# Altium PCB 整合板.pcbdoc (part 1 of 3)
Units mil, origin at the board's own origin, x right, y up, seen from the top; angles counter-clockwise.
Board outline 5095 x 5568.76 mil, 2 copper layers (Top Layer, Bottom Layer); 124 components, 78 nets, 425 pads, 497 vias.
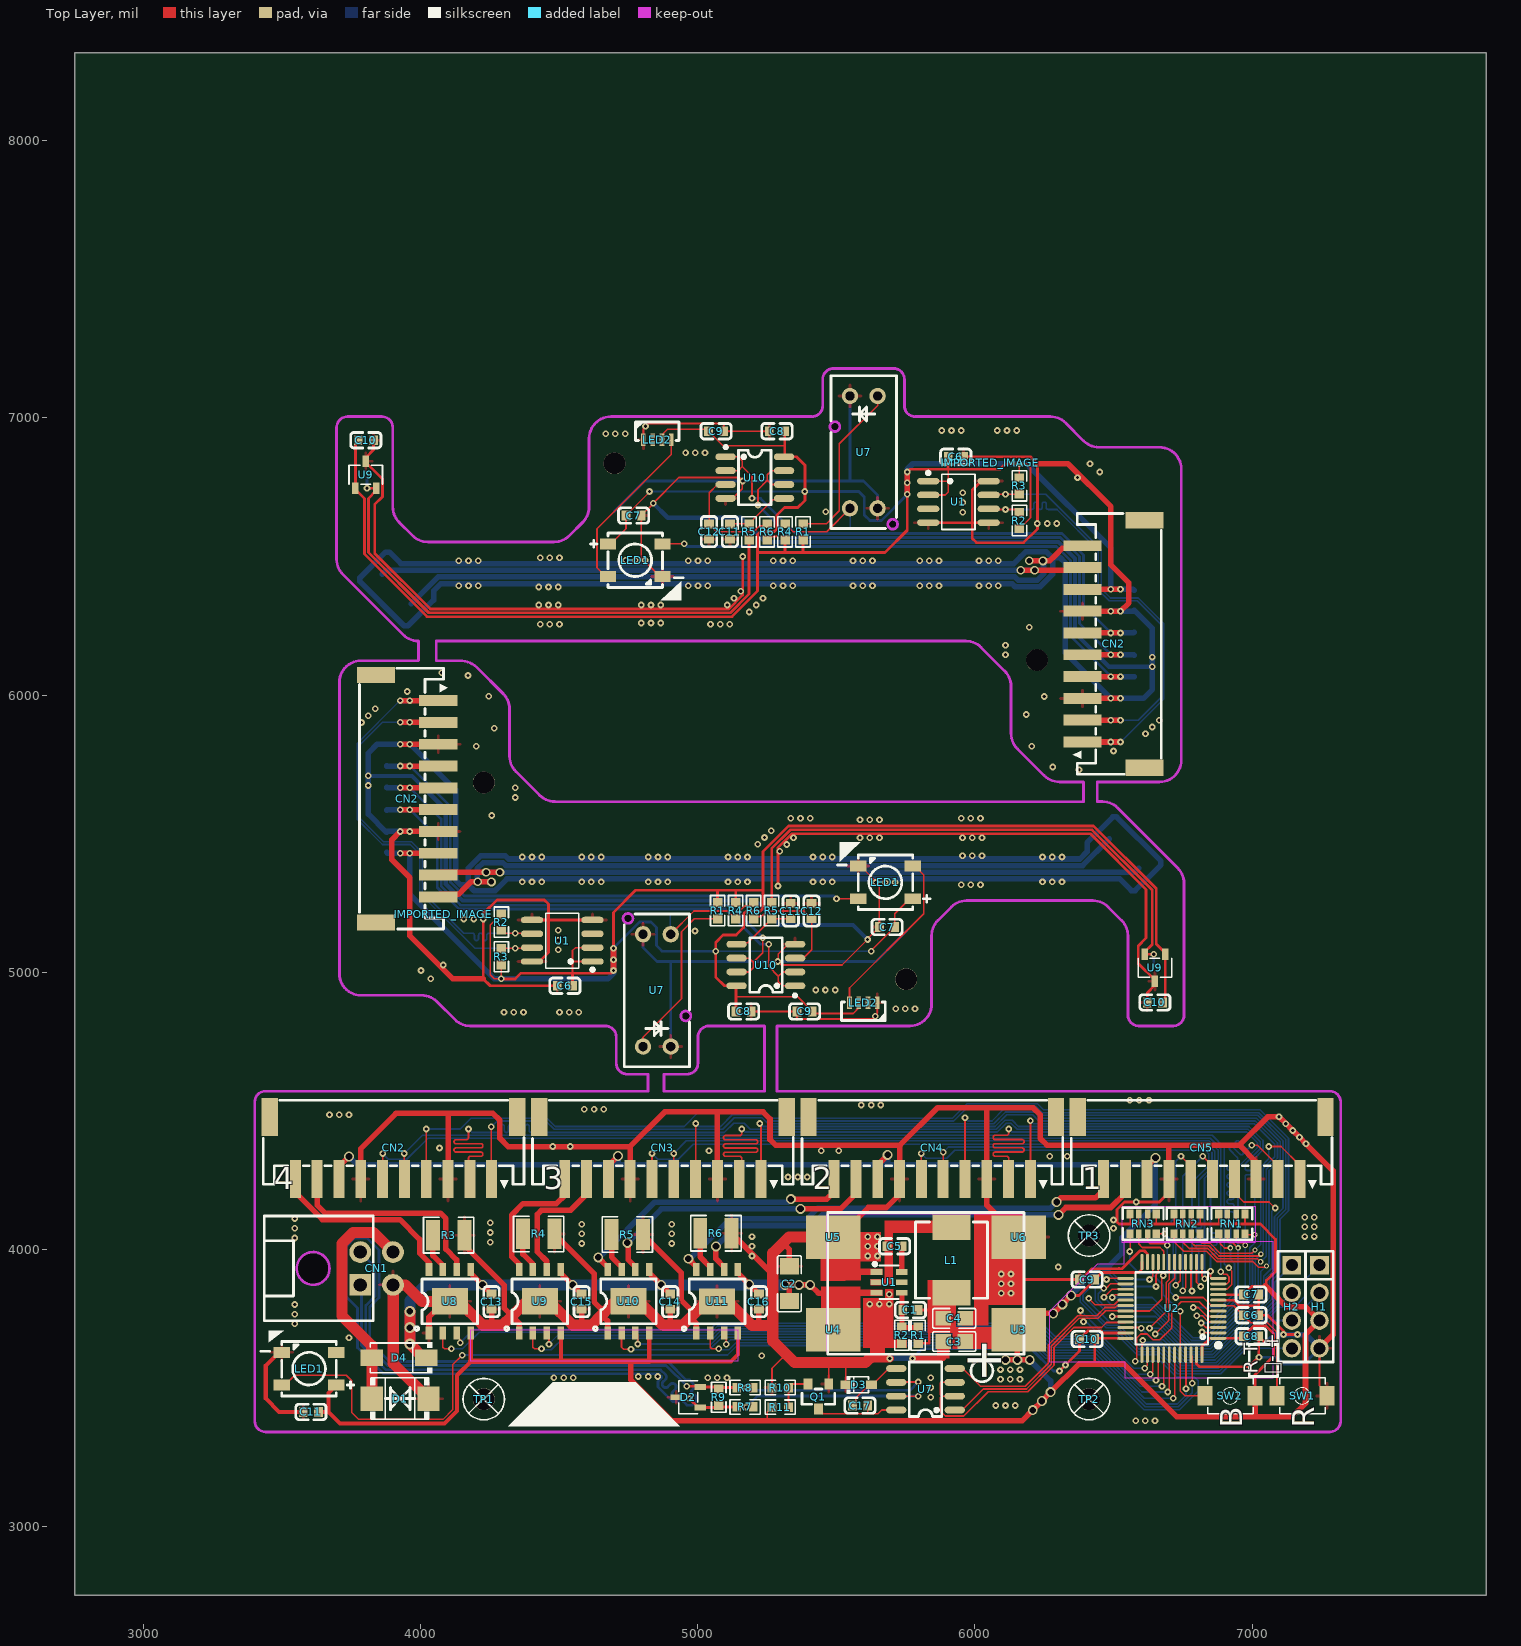
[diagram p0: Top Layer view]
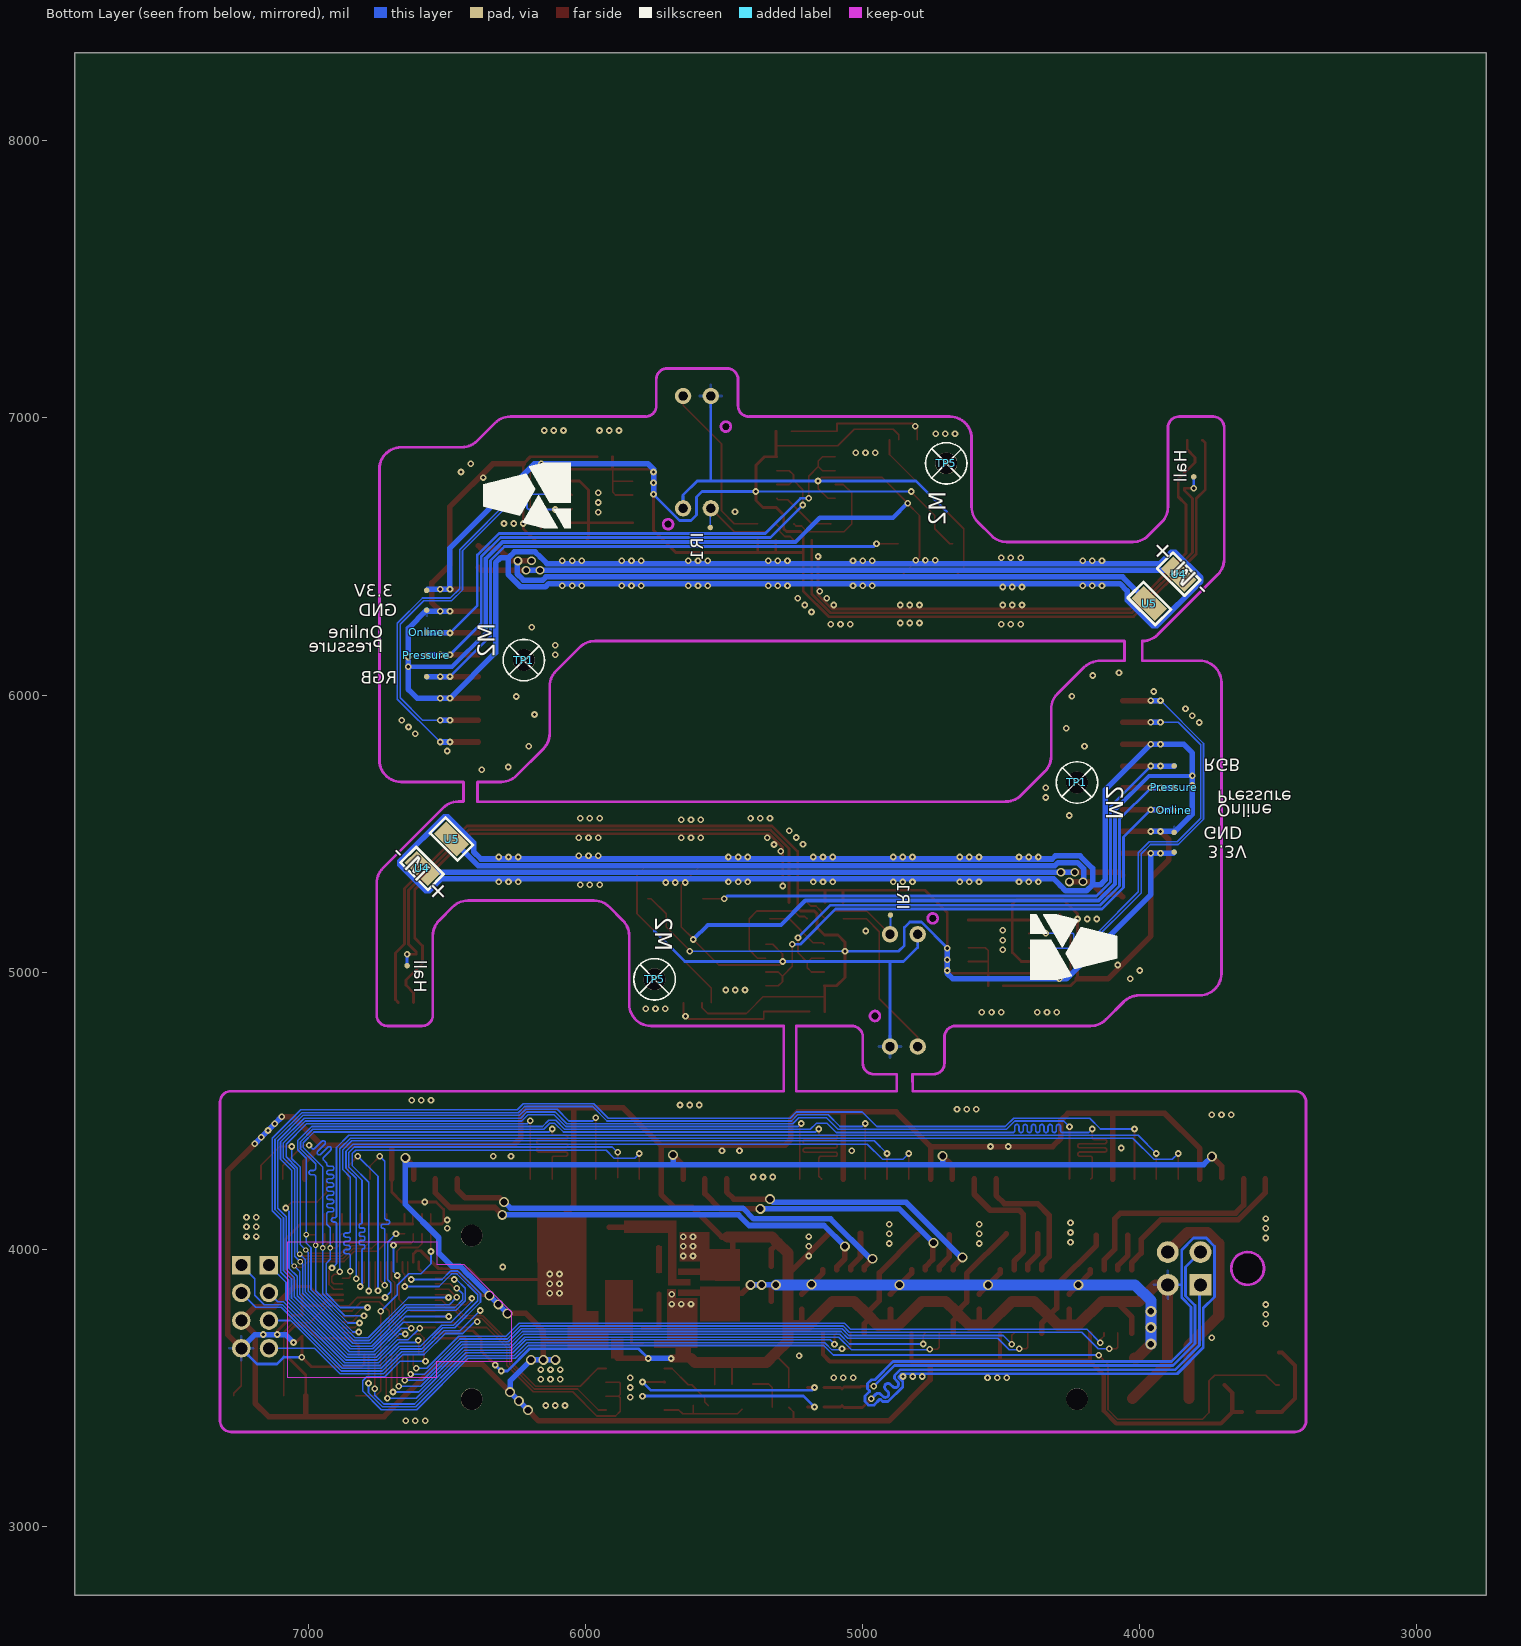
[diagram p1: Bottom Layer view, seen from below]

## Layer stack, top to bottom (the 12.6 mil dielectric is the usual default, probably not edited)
Top Layer: signal copper (thickness not stored)
Dielectric: dielectric 12.6, FR-4, Dk 4.8
Bottom Layer: signal copper (thickness not stored)

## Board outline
7845,2750 2750,2750 2750,8318.76 7845,8318.76

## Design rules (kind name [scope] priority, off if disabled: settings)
BoardOutlineClearance copperThickness1oz [All] p0: genericclearance=10 ignorepadtopadclearanceinfootprint=FALSE except(0: Arc-SplitContinuation Track-SplitContinuation SMDPad-SplitContinuation THPad-SplitContinuation Via-SplitContinuation Fill-SplitContinuation Poly-SplitContinuation Region-SplitContinuation Text-SplitContinuation; 6: Track-CutoutEdge SMDPad-CutoutEdge THPad-CutoutEdge Via-CutoutEdge Region-CutoutEdge; 11.8: Track-OutlineEdge SMDPad-OutlineEdge THPad-OutlineEdge Via-OutlineEdge Fill-OutlineEdge Region-OutlineEdge Poly-OutlineEdge Text-OutlineEdge Fill-CutoutEdge)
BoardOutlineClearance copperThickness2oz [All] p0: genericclearance=10 ignorepadtopadclearanceinfootprint=FALSE except(0: Arc-SplitContinuation Track-SplitContinuation SMDPad-SplitContinuation THPad-SplitContinuation Via-SplitContinuation Fill-SplitContinuation Poly-SplitContinuation Region-SplitContinuation Text-SplitContinuation; 6: Track-CutoutEdge SMDPad-CutoutEdge THPad-CutoutEdge Via-CutoutEdge Region-CutoutEdge; 11.8: Track-OutlineEdge SMDPad-OutlineEdge THPad-OutlineEdge Via-OutlineEdge Fill-OutlineEdge Region-OutlineEdge Poly-OutlineEdge Text-OutlineEdge Fill-CutoutEdge)
Clearance copperThickness1oz [(InNet('MCU_SCL') OR InNet('MCU_SDA') OR InNet('GND') OR InNet('RGB_OUT') OR InNet('K_PULL') OR InNet('K_ONLINE') OR InNet('3.3V') OR InNet('HALL_OUT') OR InNet('$1N10852') OR InNet('MOTOR_HOUT') OR InNet('MOTOR_LOUT') OR InNet('IR1_RECV') OR InNet('IR1_RC') OR InNet('HALL_RC') OR InNet('$1N13047') OR InNet('$1N2756') OR InNet('$1N32182') OR InNet('MCU_RX') OR InNet('$1N22933') OR InNet('RS485_B') OR InNet('$1N32139') OR InNet('$1N1340') OR InNet('MCU_RTS') OR InNet('BOOT0') OR InNet('MOTOR3_L') OR InNet('MOTOR3_H') OR InNet('$1N22936') OR InNet('RS485_A') OR InNet('MOTOR4_H') OR InNet('NRST') OR InNet('MOTOR2_L') OR InNet('SYS_RGB') OR InNet('MOTOR4_L') OR InNet('$1N32717') OR InNet('MOTOR2_H') OR InNet('MOTOR1_L') OR InNet('MCU_TX') OR InNet('MOTOR1_H') OR InNet('24V') OR InNet('SWCLK') OR InNet('MCU_SDA1') OR InNet('RGB_OUT1') OR InNet('SWIO') OR InNet('MCU_SDA2') OR InNet('$1N6554') OR InNet('RGB_OUT2') OR InNet('MCU_SDA3') OR InNet('MCU_SDA4') OR InNet('RGB_OUT4') OR InNet('RGB_OUT3') OR InNet('MCU_SCL4') OR InNet('MCU_SCL3') OR InNet('K_PULL1') OR InNet('K_PULL4') OR InNet('K_ONLINE3') OR InNet('MCU_SCL2') OR InNet('K_PULL3') OR InNet('K_ONLINE1') OR InNet('K_ONLINE4') OR InNet('EXIT_TX') OR InNet('$1N2752') OR InNet('MCU_SCL1') OR InNet('EXIT_RX') OR InNet('K_PULL2') OR InNet('K_ONLINE2') OR InNet('$1N18276') OR InNet('MOTOR4_LOUT') OR InNet('MOTOR4_HOUT') OR InNet('$1N18070') OR InNet('MOTOR3_HOUT') OR InNet('MOTOR3_LOUT') OR InNet('$1N17664') OR InNet('MOTOR2_LOUT') OR InNet('$1N17864') OR InNet('MOTOR1_LOUT') OR InNet('MOTOR2_HOUT') OR InNet('MOTOR1_HOUT') OR InNet('BOOT1'))] p1: gap=7 ignorepadtopadclearanceinfootprint=FALSE except(4: Track-Track; 6: Track-SMDPad SMDPad-SMDPad Track-THPad SMDPad-THPad THPad-THPad Track-Via SMDPad-Via THPad-Via Via-Via SMDPad-Fill THPad-Fill Via-Fill Fill-Fill Track-Region SMDPad-Region THPad-Region Via-Region Region-Region Track-Poly SMDPad-Poly THPad-Poly Via-Poly Fill-Poly Region-Poly Poly-Poly Track-Text SMDPad-Text THPad-Text Via-Text Fill-Text Region-Text Poly-Text Text-Text; 6.9: Track-Hole SMDPad-Hole THPad-Hole Via-Hole Fill-Hole Region-Hole Poly-Hole Text-Hole Sheet-Hole; 11.8: Track-Fill Fill-Region Track-Sheet SMDPad-Sheet THPad-Sheet Via-Sheet Fill-Sheet Region-Sheet Poly-Sheet Text-Sheet)
Clearance copperThickness2oz [All] p1: gap=7 ignorepadtopadclearanceinfootprint=FALSE except(6: Track-SMDPad SMDPad-SMDPad Track-THPad SMDPad-THPad THPad-THPad Track-Via SMDPad-Via THPad-Via Via-Via SMDPad-Fill THPad-Fill Via-Fill Fill-Fill Track-Region SMDPad-Region THPad-Region Via-Region Region-Region Track-Poly SMDPad-Poly THPad-Poly Via-Poly Fill-Poly Region-Poly Poly-Poly Track-Text SMDPad-Text THPad-Text Via-Text Fill-Text Region-Text Poly-Text Text-Text; 6.9: Track-Hole SMDPad-Hole THPad-Hole Via-Hole Fill-Hole Region-Hole Poly-Hole Text-Hole Sheet-Hole; 8: Track-Track; 11.8: Track-Fill Fill-Region Track-Sheet SMDPad-Sheet THPad-Sheet Via-Sheet Fill-Sheet Region-Sheet Poly-Sheet Text-Sheet)
DiffPairsRouting differentialPair [All] p1: maxuncoupledlength=10 minlimit=6 maxlimit=6 mostfreqgap=6 toplayer_minwidth=5 toplayer_prefwidth=10 toplayer_maxwidth=100 bottomlayer_minwidth=5 bottomlayer_prefwidth=10 bottomlayer_maxwidth=100
PasteMaskExpansion pasteMaskExpansion [All] p1: expansion=0
PlaneConnect innerPlane [All] p1: planeconnectstyle=Relief reliefexpansion=20 reliefentries=4 reliefconductorwidth=10 reliefairgap=10
PolygonConnect copperRegion [All] p1: connectstyle=Relief reliefentries=4 reliefconductorwidth=10 polygonreliefangle="90 Angle" airgapwidth=10
RoutingVias viaSize [All] p1: viastyle="Through Hole" holewidth=12.0078 minholewidth=11.811 maxholewidth=248.0314 width=24.0158 minwidth=19.685 maxwidth=393.7008
SolderMaskExpansion solderMaskExpansion [All] p1: useseparateexpansions=TRUE expansion=2 expansionbottom=2
Width copperThickness1oz [All] p1: maxlimit=100 minlimit=5 preferedwidth=10
Width copperThickness2oz [All] p1: maxlimit=100 minlimit=8 preferedwidth=10

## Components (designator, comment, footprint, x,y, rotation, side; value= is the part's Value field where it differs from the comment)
3.3V "" Test-Point-0.5mm 6574.32,6377.59 r270 bottom
3.3V "" Test-Point-0.5mm 3876.06,5432.64 r90 bottom
C1 "" C0603 5767,3780 r0 top
C2 "" C1206 5330,3875 r270 top
C3 "" C0805 5925,3666.12 r0 top
C4 "" C0805 5925,3750 r180 top
C5 "" C0603 5710,4010 r180 top
C6 "" C0603 5930.62,6859.93 r180 top
C6 "" C0603 4519.76,4950.31 r0 top
C6 "" C0603 6996.85,3760.93 r180 top
C7 "" C0603 4767.87,6647.72 r180 top
C7 "" C0603 5682.51,5162.52 r0 top
C7 "" C0603 6996.85,3835.93 r180 top
C8 "" C0603 5285.31,6952.44 r0 top
C8 "" C0603 5165.07,4857.8 r180 top
C8 "" C0603 6996.85,3685.29 r180 top
C9 "" C0603 5065.31,6952.44 r180 top
C9 "" C0603 5385.07,4857.79 r0 top
C9 "" C0603 6405,3890 r0 top
C10 "" C0603 3800.94,6919.93 r180 top
C10 "" C0603 6649.44,4890.31 r0 top
C10 "" C0603 6405,3675 r0 top
C11 "" C0603 5115.31,6589.92 r90 top
C11 "" C0603 5335.07,5220.31 r270 top
C11 "" C0603 3602.97,3412.12 r0 top
C12 "" C0603 5040.19,6589.92 r90 top
C12 "" C0603 5410.19,5220.31 r270 top
C13 "" C0603 4255,3810 r90 top
C14 "" C0603 4900,3810.04 r90 top
C15 "" C0603 4580,3810.08 r90 top
C16 "" C0603 5220,3810.13 r90 top
C17 "" C0603 5585,3435 r0 top
CN1 "" CONN-TH_4P-P3.00_HC-MX3.0-2X2AW_1 3840,3930 r270 top
CN2 "" CONN-SMD_10P-P2.00_2.0-10P-WT 6500.3,6184.67 r90 top
CN2 "" CONN-SMD_10P-P2.00_2.0-10P-WT 3950.08,5625.56 r270 top
CN2 "" CONN-SMD_10P-P2.00_2.0-10P-WT 3900.91,4365.01 r180 top
CN3 "" CONN-SMD_10P-P2.00_2.0-10P-WT 4873.35,4365.01 r180 top
CN4 "" CONN-SMD_10P-P2.00_2.0-10P-WT 5845.79,4365.01 r180 top
CN5 "" CONN-SMD_10P-P2.00_2.0-10P-WT 6818.23,4365.01 r180 top
D1 "" SMB_L4.6-W3.6-LS5.3-BI 3925,3460 r180 top
D2 "" SOT-23-3_L3.0-W1.7-P0.95-LS2.9-BR 4965,3465 r0 top
D3 "" SOD-323_L1.8-W1.3-LS2.5-RD 5580,3510 r0 top
D4 "" SMA_L4.4-W2.8-LS5.4-R-RD 3920.92,3607.43 r180 top
GND "" Test-Point-0.5mm 6574.32,6306.18 r270 bottom
GND "" Test-Point-0.5mm 3876.06,5504.05 r90 bottom
H1 "" HDR-TH_4P-P2.54-V-M 7243.61,3791.82 r270 top
H2 "" HDR-TH_4P-P2.54-V-M 7143.61,3791.82 r270 top
Hall "" Test-Point-0.5mm 3805.41,6787.21 r90 bottom
Hall "" Test-Point-0.5mm 6644.97,5023.02 r270 bottom
IMPORTED_IMAGE "IMPORTED_IMAGE" IMPORTED_IMAGE 6054.73,6838.62 r0 top
IMPORTED_IMAGE "IMPORTED_IMAGE" IMPORTED_IMAGE 4081.07,5207.84 r0 top
IR1 "" Test-Point-0.5mm 5550.31,6604.6 r270 bottom
IR1 "" Test-Point-0.5mm 4900.07,5205.63 r90 bottom
L1 "" IND-SMD_L7.3-W6.8 5915,3960 r270 top
LED1 "" LED-SMD_4P-L5.0-W5.0-BL_XL-5050RGBC 4773.69,6486.47 r270 top
LED1 "" LED-SMD_4P-L5.0-W5.0-BL_XL-5050RGBC 5676.69,5323.76 r90 top
LED1 "" LED-SMD_4P-L5.0-W5.0-BL_XL-5050RGBC 3596.03,3568.08 r90 top
LED2 "" LED-SMD_4P-L4.0-W1.7_XL-4020RGBC-WS2812B 4853.18,6921.42 r180 top
LED2 "" LED-SMD_4P-L4.0-W1.7_XL-4020RGBC-WS2812B 5597.2,4888.81 r0 top
Online "" Test-Point-0.5mm 6574.32,6226.18 r270 bottom
Online "" Test-Point-0.5mm 3876.06,5584.05 r90 bottom
Pressure "" Test-Point-0.5mm 6574.32,6143.89 r180 bottom
Pressure "" Test-Point-0.5mm 3876.06,5666.34 r0 bottom
Q1 "" SOT-23_L2.9-W1.3-P1.90-LS2.4-BR 5435,3467.57 r90 top
R1 "" R0603 5379.39,6588.76 r90 top
R1 "" R0603 5070.99,5221.47 r270 top
R1 "" R0603 5795,3689 r270 top
R2 "" R0603 6160.31,6629.93 r90 top
R2 "" R0603 4290.07,5180.31 r270 top
R2 "" R0603 5736,3689 r90 top
R3 "" R0603 6160.31,6754.93 r270 top
R3 "" R0603 4290.07,5055.31 r90 top
R3 "" R1210 4100,4050 r0 top
R4 "" R0603 5314.39,6588.76 r90 top
R4 "" R0603 5135.99,5221.47 r270 top
R4 "" R1210 4425,4054.68 r0 top
R5 "" R0603 5184.39,6588.76 r90 top
R5 "" R0603 5265.99,5221.47 r270 top
R5 "" R1210 4745,4052.34 r0 top
R6 "" R0603 5249.39,6588.76 r270 top
R6 "" R0603 5200.99,5221.47 r90 top
R6 "" R1210 5065,4057.02 r0 top
R7 "" R0603 5170,3430 r180 top
R8 "" R0603 5170,3500 r180 top
R9 "" R0603 5075,3465 r270 top
R10 "" R0603 5297.2,3500 r0 top
R11 "" R0603 5297.2,3429.1 r0 top
RGB "" Test-Point-0.5mm 6574.32,6066.18 r270 bottom
RGB "" Test-Point-0.5mm 3876.06,5744.05 r90 bottom
RN1 "" RES-ARRAY-SMD_0603-8P-L3.2-W1.6-BL 6927.14,4090.93 r0 top
RN2 "" RES-ARRAY-SMD_0603-8P-L3.2-W1.6-BL 6765.7,4090.93 r0 top
RN3 "" RES-ARRAY-SMD_0603-8P-L3.2-W1.6-BL 6607.14,4090.93 r0 top
SW1 "" KEY-SMD_B3U-1000PM 7180,3470 r0 top
SW2 "" KEY-SMD_B3U-1000PM 6920,3470 r0 top
TP1 "" M2螺丝 6223.64,6126.02 r270 bottom
TP1 "" M2螺丝 4226.74,5684.22 r90 bottom
TP1 "" M2螺丝 4226.77,3458.11 r90 top
TP2 "" M2螺丝 6411.81,3458.11 r90 top
TP3 "" M2螺丝 6411.81,4048.66 r90 top
TP5 "" M2螺丝 4698.61,6836.42 r270 bottom
TP5 "" M2螺丝 5751.77,4973.81 r90 bottom
U1 "" SOIC-8_L4.9-W3.9-P1.27-LS6.0-BL 5940.31,6697.22 r270 top
U1 "" SOIC-8_L4.9-W3.9-P1.27-LS6.0-BL 4510.07,5113.02 r90 top
U1 "={Manufacturer Part}" SOT-23-6_L2.9-W1.6-P0.95-LS2.8-BL 5690,3880 r270 top
U2 "" LQFP-48_L7.0-W7.0-P0.50-LS9.0-BL 6711.03,3785.96 r90 top
U3 "" "SMD 方焊盘 4*5" 6157.59,3708.59 r270 top
U4 "" TEST-RING 3859.6,6436.12 r225 bottom
U4 "" TEST-RING 6590.78,5374.11 r45 bottom
U4 "" "SMD 方焊盘 4*5" 5488.3,3708.59 r270 top
U5 "" TEST-RING 3965.66,6330.05 r225 bottom
U5 "" TEST-RING 6484.72,5480.18 r45 bottom
U5 "" "SMD 方焊盘 4*5" 5488.3,4043.23 r90 top
U6 "" "SMD 方焊盘 4*5" 6157.59,4043.23 r90 top
U7 "" OPTO-TH_4P_ITR9606 5598.58,6876.66 r270 top
U7 "" OPTO-TH_4P_ITR9606 4851.8,4933.58 r90 top
U7 "" SOP-8_L4.9-W3.9-P1.27-LS6.0-BL 5821.23,3493.8 r90 top
U8 "" ESOP-8_L4.9-W3.9-P1.27-LS6.0-BL-EP 4104.08,3811.35 r0 top
U9 "" SOT-23-3_L2.9-W1.6-P1.90-LS2.8-BR 3800.94,6794.93 r270 top
U9 "" SOT-23-3_L2.9-W1.6-P1.90-LS2.8-BR 6649.44,5015.31 r90 top
U9 "" ESOP-8_L4.9-W3.9-P1.27-LS6.0-BL-EP 4429.08,3811.27 r0 top
U10 "" SOP-8_L4.9-W3.9-P1.27-LS6.0-BL 5205.31,6784.93 r270 top
U10 "" SOP-8_L4.9-W3.9-P1.27-LS6.0-BL 5245.07,5025.31 r90 top
U10 "" ESOP-8_L4.9-W3.9-P1.27-LS6.0-BL-EP 4749.08,3811.31 r0 top
U11 "" ESOP-8_L4.9-W3.9-P1.27-LS6.0-BL-EP 5069.08,3811.23 r0 top

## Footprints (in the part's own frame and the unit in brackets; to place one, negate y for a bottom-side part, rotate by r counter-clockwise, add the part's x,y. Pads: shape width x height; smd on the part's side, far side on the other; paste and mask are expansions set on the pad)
C0603 [mm]
  rect 0.8x0.9 smd: 1(-0.7,0) 2(0.7,0)
  silkscreen extent -1.39,-0.71 1.39,0.71
C0805 [mm]
  rect 1.41x1.35 smd: 1(-1,0) 2(1,0)
  silkscreen extent -1.96,-0.9 1.96,0.9
C1206 [mm]
  rect 1.485x1.728 smd: 1(-1.593,0) 2(1.593,0)
  silkscreen extent -2.56,-1.09 2.56,1.09
CONN-SMD_10P-P2.00_2.0-10P-WT [mm]
  rect 1x3.5 smd: 1(-9,2.85) 2(-7,2.85) 3(-5,2.85) 4(-3,2.85) 5(-1,2.85) 6(1,2.85) 7(3,2.85) 8(5,2.85) 9(7,2.85) 10(9,2.85)
  rect 1.5x3.5 smd: 11(11.35,-2.85) 12(-11.35,-2.85)
  silkscreen extent -11.96,-4.37 11.95,3.74
CONN-TH_4P-P3.00_HC-MX3.0-2X2AW_1 [mm]
  rect 2x2 hole 1.2: 1(1.5,-1.5)
  round 2 hole 1.2: 2(1.5,1.5) 3(-1.5,-1.5) 4(-1.5,1.5)
  Board Outline Layer circle w0.005: c0,-5.82 r1.5
  Board Outline Layer circle w0.254: c0,-5.82 r1.5
  Multi-Layer board cut-out: 0,-4.32 -0.651,-4.469 -1.173,-4.885 -1.462,-5.486 -1.462,-6.154 -1.173,-6.755 -0.651,-7.171 0,-7.32 0,-7.32 0.75,-7.119 1.299,-6.57 1.5,-5.82 1.299,-5.07 0.75,-4.521 0,-4.32
  silkscreen extent -4.8,-10.3 4.8,-0.3
ESOP-8_L4.9-W3.9-P1.27-LS6.0-BL-EP [mm]
  rect 0.6x1.2 smd: 1(-1.905,-2.908) 2(-0.635,-2.908) 3(0.635,-2.908) 4(1.905,-2.908) 5(1.905,2.908) 6(0.635,2.908) 7(-0.635,2.908) 8(-1.905,2.908)
  rect 3.3x2.4 smd: 9(0,0)
  silkscreen extent -3.2,-2.67 2.55,2.05
HDR-TH_4P-P2.54-V-M [mm]
  rect 1.7x1.7 hole 1.1: 1(-3.81,0)
  round 1.7 hole 1.1: 2(-1.27,0) 3(1.27,0) 4(3.81,0)
  silkscreen extent -5.08,-1.27 5.08,1.27
IMPORTED_IMAGE [mil]
IND-SMD_L7.3-W6.8 [mm]
  rect 2.35x3.5 smd: 1(-3,0) 2(3,0)
  silkscreen extent -3.5,-3.3 3.5,3.3
KEY-SMD_B3U-1000PM [mm]
  rect 1.4x1.8 smd: 1(-2.286,0) 2(2.314,0)
  silkscreen extent -2.04,-1.65 2.16,1.65
LED-SMD_4P-L4.0-W1.7_XL-4020RGBC-WS2812B [mm]
  rect 0.43x1.15 smd: 1(1.275,0) 2(0.425,0) 3(-0.425,0) 4(-1.275,0)
  silkscreen extent -2,-1.62 2,0.08
LED-SMD_4P-L5.0-W5.0-BL_XL-5050RGBC [mm]
  rect 1x1.5 smd: 1(-1.5,-2.5) 2(1.5,-2.5) 3(1.5,2.5) 4(-1.5,2.5)
  silkscreen extent -2.5,-4.1 2.5,4.4
LQFP-48_L7.0-W7.0-P0.50-LS9.0-BL [mm]
  oval 0.27x1.5 smd: 1(-2.75,-4.25) 2(-2.25,-4.25) 3(-1.75,-4.25) 4(-1.25,-4.25) 5(-0.75,-4.25) 6(-0.25,-4.25) 7(0.25,-4.25) 8(0.75,-4.25) 9(1.25,-4.25) 10(1.75,-4.25) 11(2.25,-4.25) 12(2.75,-4.25) 25(2.75,4.25) 26(2.25,4.25) 27(1.75,4.25) 28(1.25,4.25) 29(0.75,4.25) 30(0.25,4.25) 31(-0.25,4.25) 32(-0.75,4.25) 33(-1.25,4.25) 34(-1.75,4.25) 35(-2.25,4.25) 36(-2.75,4.25)
  oval 1.5x0.27 smd: 13(4.25,-2.75) 14(4.25,-2.25) 15(4.25,-1.75) 16(4.25,-1.25) 17(4.25,-0.75) 18(4.25,-0.25) 19(4.25,0.25) 20(4.25,0.75) 21(4.25,1.25) 22(4.25,1.75) 23(4.25,2.25) 24(4.25,2.75) 37(-4.25,2.75) 38(-4.25,2.25) 39(-4.25,1.75) 40(-4.25,1.25) 41(-4.25,0.75) 42(-4.25,0.25) 43(-4.25,-0.25) 44(-4.25,-0.75) 45(-4.25,-1.25) 46(-4.25,-1.75) 47(-4.25,-2.25) 48(-4.25,-2.75)
  silkscreen extent -3.59,-4.46 3.3,3.34
M2螺丝 [mm]
  round 2 hole 2: 1(0,0)
  silkscreen extent -1.9,-1.9 1.9,1.9
OPTO-TH_4P_ITR9606 [mil]
  round 59.06 hole 32 slot 32.2 at 0 deg: 1(-202.76,50) 2(-202.76,-50)
  round 59.06 hole 32 slot 32.2 at 0 deg copper offset 0.02,0: 3(202.74,-50) 4(202.74,50)
  Board Outline Layer circle w0.2: c260.12,104.33 r17.72
  Board Outline Layer circle w0.2: c-92.28,-104.33 r17.72
  Board Outline Layer circle w10: c260.12,104.33 r17.72
  Board Outline Layer circle w10: c-92.28,-104.33 r17.72
  Multi-Layer board cut-out: 260.12,122.05 252.43,120.29 246.27,115.38 242.84,108.27 242.84,100.39 246.26,93.28 252.43,88.37 260.12,86.61 260.12,86.61 267.8,88.37 273.97,93.28 277.39,100.39 277.39,108.27 273.97,115.38 267.81,120.29 260.12,122.05
  Multi-Layer board cut-out: -92.28,-86.61 -101.1,-89.02 -107.54,-95.5 -109.9,-104.33 -107.54,-113.16 -101.1,-119.64 -92.28,-122.05 -92.28,-122.05 -83.47,-119.64 -77.03,-113.16 -74.67,-104.33 -77.03,-95.5 -83.47,-89.02 -92.28,-86.61
  silkscreen extent -276,-118 276,118
R0603 [mil]
  rect 31.75x34.02 smd: 1(-29.66,0) 2(29.66,0)
  silkscreen extent -55,-26 55,26
R1210 [mil]
  rect 50.49x110.55 smd: 1(-56.74,0) 2(56.74,0)
  silkscreen extent -91,-64 91,64
RES-ARRAY-SMD_0603-8P-L3.2-W1.6-BL [mm]
  rect 0.65x0.8 smd: 1(-1.2,-0.9) 4(1.2,-0.9) 5(1.2,0.9) 8(-1.2,0.9)
  rect 0.5x0.8 smd: 2(-0.4,-0.9) 3(0.4,-0.9) 6(0.4,0.9) 7(-0.4,0.9)
  silkscreen extent -1.87,-1.45 1.87,1.47
SMA_L4.4-W2.8-LS5.4-R-RD [mil]
  rect 81.2x60.59 smd: 1(98.57,0) 2(-98.57,0)
  silkscreen extent -119,-56 104,56
SMB_L4.6-W3.6-LS5.3-BI [mil]
  rect 80.61x88.23 smd: 1(-102.02,0) 2(102.02,0)
  silkscreen extent -105,-75 108,75
"SMD 方焊盘 4*5" [mm]
  rect 4x5 smd: 1(0,0)
SOD-323_L1.8-W1.3-LS2.5-RD [mm]
  rect 1x0.75 smd: 1(-1.173,0) 2(1.173,0)
  silkscreen extent -1.08,-0.8 0.9,0.8
SOIC-8_L4.9-W3.9-P1.27-LS6.0-BL [mm]
  oval 0.588x2.045 smd: 1(-1.905,-2.772) 2(-0.635,-2.772) 3(0.635,-2.772) 4(1.905,-2.772) 5(1.905,2.772) 6(0.635,2.772) 7(-0.635,2.772) 8(-1.905,2.772)
  silkscreen extent -2.8,-2.92 2.53,1.52
SOP-8_L4.9-W3.9-P1.27-LS6.0-BL [mm]
  oval 0.63x1.865 smd: 1(-1.905,-2.682) 2(-0.635,-2.682) 3(0.635,-2.682) 4(1.905,-2.682) 5(1.905,2.682) 6(0.635,2.682) 7(-0.635,2.682) 8(-1.905,2.682)
  silkscreen extent -2.5,-1.5 2.5,1.48
SOT-23-3_L2.9-W1.6-P1.90-LS2.8-BR [mm]
  rect 1.07x0.6 smd: 1(1.235,-0.95) 2(1.235,0.95) 3(-1.235,0)
  silkscreen extent -0.88,-1.54 0.88,1.54
SOT-23-3_L3.0-W1.7-P0.95-LS2.9-BR [mil]
  rect 40.85x20.95 smd: 1(43.36,-37.4) 2(43.36,37.4) 3(-43.36,0)
  silkscreen extent -34,-60 34,60
SOT-23-6_L2.9-W1.6-P0.95-LS2.8-BL [mil]
  rect 20.95x42.2 smd: 1(-37.4,-45.24) 2(0,-45.24) 3(37.4,-45.24) 4(37.4,45.24) 5(0,45.24) 6(-37.4,45.24)
  silkscreen extent -72,-57 61,35
SOT-23_L2.9-W1.3-P1.90-LS2.4-BR [mm]
  rect 1x0.8 smd: 1(1.15,-0.95) 2(1.15,0.95) 3(-1.15,0)
  silkscreen extent -0.7,-1.5 0.7,1.5
Test-Point-0.5mm [mm]
  round 0.5 smd: 1(0,0)
TEST-RING [mm]
  rect 3x1.6 smd: 1(0,0)
  silkscreen extent -1.78,-1.02 1.78,1.02

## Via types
v1: diameter 24.02, hole 12.01, Top Layer to Bottom Layer, 450 vias
v2: diameter 36, hole 24, Top Layer to Bottom Layer, 28 vias
v3: diameter 32, hole 20, Top Layer to Bottom Layer, 8 vias
v4: diameter 19.68, hole 11.81, Top Layer to Bottom Layer, 8 vias
v5: diameter 40, hole 24, Top Layer to Bottom Layer, 3 vias

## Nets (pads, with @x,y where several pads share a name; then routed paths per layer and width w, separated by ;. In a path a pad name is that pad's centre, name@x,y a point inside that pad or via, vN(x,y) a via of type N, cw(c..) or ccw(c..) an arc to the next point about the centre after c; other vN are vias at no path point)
3.3V: 3.3V.1 C1.2 C3.2 C4.2 C6.2@4547.32,4950.31 C6.2@5903.06,6859.93 C7.2 C8.2 C9.2 C10.2 C11.2@3630.53,3412.12 CN2.8 CN3.8 CN4.8 CN5.8 H1.3 L1.2 LED1.1 LED2.3 R1.1@5070.99,5251.13 R1.1@5379.39,6559.1 R1.2@5795,3659.34 R2.1@4290.07,5209.97 R2.1@6160.31,6600.27 R3.1@4290.07,5025.65 R3.1@6160.31,6784.59 R4.1@5135.99,5251.13 R4.1@5314.39,6559.1 R11.1 RN1.5 RN1.6 RN1.7 RN1.8 RN2.5 RN2.6 RN2.7 RN2.8 RN3.5 RN3.6 SW2.2 U1.1@4619.22,5038.02 U1.1@5831.16,6772.22 U1.2@4619.22,5088.02 U1.2@5831.16,6722.22 U2.1 U2.9 U2.24 U2.36 U2.48 U3.1 U8.4 U9.1@3763.54,6746.3 U9.1@6686.84,5063.93 U9.4 U10.4@4824.08,3696.81 U10.8@5139.46,4950.31 U10.8@5310.92,6859.93 U11.4 | length 29101
  Top Layer w6: R3.1@4290.07,5025.65 4290.2,5025.53 v1(4290.2,4975.31) 4265.07,4975.31 4250.07,4990.31 4250.07,5169.97 R2.1@4290.07,5209.97 ; 4547.32,4995.31 4547.32,5038.02 ; U1.1@4619.22,5038.02 4547.32,5038.02 ; U1.2@4619.22,5088.02 4557.78,5088.02 4547.32,5077.56 4547.32,5038.02 ; LED1.1@4675.27,6545.52 4685.9,6545.52 4740.31,6599.93 C7.2@4740.31,6647.72 4825.31,6732.72 v1(4825.31,6734.93) ; LED2.3@4869.91,6921.42 4869.91,6939.53 4890.31,6959.93 5030.26,6959.93 C9.2@5037.75,6952.44 5090.36,6899.82 5312.87,6899.82 ; 5137.51,4910.41 5360.02,4910.41 C9.2@5412.63,4857.79 5420.12,4850.31 5560.07,4850.31 5580.47,4870.71 LED2.3@5580.47,4888.81 ; U10.8@5137.51,4948.36 U10.8@5139.46,4950.31 ; 5250,3380 5250,3411.57 R11.1@5267.54,3429.1 ; U10.8@5310.92,6859.93 U10.8@5312.87,6861.88 ; v1(5625.07,5075.31) 5625.07,5077.52 C7.2@5710.07,5162.52 5710.07,5210.31 5764.48,5264.71 LED1.1@5775.11,5264.71 ; U1.2@5831.16,6722.22 5892.6,6722.22 5903.06,6732.68 5903.06,6772.22 ; U1.1@5831.16,6772.22 5903.06,6772.22 ; 5903.06,6814.93 5903.06,6772.22 ; R2.1@6160.31,6600.27 6200.31,6640.27 6200.31,6819.93 6185.31,6834.93 v1(6160.19,6834.93) 6160.19,6784.71 R3.1@6160.31,6784.59 ; RN3.6@6622.89,4126.37 6625,4124.25 6625,4090 ; RN3.5@6654.38,4126.37 6654.38,4090.18 6654.55,4090 ; RN2.8@6718.46,4126.37 6718.99,4125.84 6718.99,4090 ; RN2.7@6749.95,4126.37 6749.95,4091.38 6751.32,4090 ; RN2.6@6781.45,4126.37 6781.45,4090.76 6782.21,4090 ; 6812.11,4090 6812.94,4090.83 RN2.5@6812.94,4126.37 ; 6879.77,4090 6879.9,4090.13 RN1.8@6879.9,4126.37 ; RN1.7@6911.39,4126.37 6914.01,4123.74 6914.01,4090 ; 6942.79,4090 6942.89,4090.09 RN1.6@6942.89,4126.37 ; RN1.5@6974.38,4126.37 6975,4125.74 6975,4090 ; 7011.1,3395.18 7011.28,3395
  Top Layer w10: C10.2@3773.38,6919.93 3763.54,6910.08 U9.1@3763.54,6746.3 3763.54,6741.7 3796.19,6709.04 3796.19,6509.04 4022.32,6282.92 5122.93,6282.92 5215.31,6375.29 5215.31,6514.93 ; v1(4290.2,4975.31) 4340.07,4975.31 4360.07,4995.31 4547.32,4995.31 ; C6.2@4547.32,4950.31 4547.32,4995.31 ; v1(4695.07,5005.31) 4685.07,4995.31 4547.32,4995.31 ; v1(4695.07,5085.31) 4695.07,5215.31 4775.07,5295.31 5070.99,5295.31 ; R1.1@5070.99,5251.13 5070.99,5295.31 ; R4.1@5135.99,5251.13 5135.99,5295.31 ; C8.2@5137.51,4857.8 5137.51,4910.41 U10.8@5137.51,4948.36 ; U10.8@5139.46,4950.31 5095.07,4950.31 5064.49,4980.89 v1(5064.49,5075.31) 5064.49,5107.65 5090.07,5133.24 5138,5133.24 5165.07,5160.31 5165.07,5210.31 5175.07,5220.31 5225.07,5220.31 5235.07,5230.31 5235.07,5295.31 ; U10.8@5310.92,6859.93 5355.31,6859.93 5385.89,6829.34 v1(5385.89,6734.93) 5385.89,6702.58 5360.31,6677 5312.38,6677 5285.31,6649.93 5285.31,6599.93 5275.31,6589.93 5225.31,6589.93 5215.31,6579.93 5215.31,6514.93 ; U10.8@5312.87,6861.88 5312.87,6899.82 C8.2@5312.87,6952.44 ; R4.1@5314.39,6559.1 5314.39,6514.93 ; R1.1@5379.39,6559.1 5379.39,6514.93 ; v1(5755.31,6724.93) 5755.31,6594.93 5675.31,6514.93 5379.39,6514.93 ; v1(5755.31,6804.93) 5765.31,6814.93 5903.06,6814.93 ; R1.2@5795,3660.34 5835,3660.34 5835,3749.93 5835,3780 C1.2@5797.56,3780 ; 5835.07,3750 C4.2@5885.63,3750 ; C6.2@5903.06,6859.93 5903.06,6814.93 ; v1(6160.19,6834.93) 6110.31,6834.93 6090.31,6814.93 5903.06,6814.93 ; v2(6347.3,3832.3) 6374.86,3832.3 C9.2@6432.56,3890 6457.56,3915 6590,3915 6602.76,3927.76 U2.24@6602.76,3953.28 ; 6432.99,3585 6432.56,3585.43 C10.2@6432.56,3675 6435.25,3677.69 U2.36@6543.71,3677.69 ; 6625,4090 6654.55,4090 6718.99,4090 6751.32,4090 6782.21,4090 6812.11,4090 6879.77,4090 6914.01,4090 6942.79,4090 6975,4090 7030,4090 7085,4035 7085,3920 7051.78,3886.78 7051.78,3864.63 6997.99,3864.63 C7.2@6969.29,3835.93 6968.53,3835.17 U2.9@6878.35,3835.17 ; C10.2@6677,4890.31 6686.84,4900.15 U9.1@6686.84,5063.93 6686.84,5068.54 6654.19,5101.19 6654.19,5301.19 6428.07,5527.32 5327.45,5527.32 5235.07,5434.94 5235.07,5295.31 ; U2.48@6819.3,3618.64 6819.3,3649.3 6847.69,3677.69 U2.1@6878.35,3677.69 6961.69,3677.69 C8.2@6969.29,3685.29 7006.22,3722.21 7050.79,3722.21 7077.98,3695.02 7077.98,3612.98 7011.1,3546.1 SW2.2@7011.1,3470 ; 5070.99,5295.31 5135.99,5295.31 ; 5135.99,5295.31 5235.07,5295.31 ; 5215.31,6514.93 5314.39,6514.93 ; 5314.39,6514.93 5379.39,6514.93
  Top Layer w15: C11.2@3630.53,3412.12 3665.53,3412.12 3666.14,3411.52 ; LED1.1@3694.46,3509.03 3666.14,3480.71 3666.14,3411.52 ; U8.4@4179.08,3696.85 4180,3695.93 4180,3594.39 4130,3544.39 4130,3415 4085,3370 3707.65,3370 3666.14,3411.52 ; U9.4@4504.08,3696.77 4505.22,3695.63 4505.22,3594.39 ; U10.4@4824.08,3696.81 4824.08,3594.47 4824.16,3594.39 5119.39,3594.39 5144.08,3619.08 U11.4@5144.08,3696.73
  Top Layer w20: CN2.8@3704.06,4257.13 3704.06,4298.27 v2(3740.12,4334.34) ; v1(3925.07,5428.71) v1(3960.07,5428.71) CN2.8@4062.29,5428.71 ; 4180,3594.39 4505.22,3594.39 4757.01,3594.39 ; CN3.8@4676.5,4252.8 4676.5,4300.94 v2(4711.57,4336.02) ; v1(4695.07,5005.31) v1(4695.07,5044.53) v1(4695.07,5085.31) ; 4824.16,3594.39 4757.01,3594.39 ; CN4.8@5648.94,4252.8 5648.94,4303.94 v2(5685,4340) ; v1(5755.31,6724.93) v1(5755.31,6765.7) v1(5755.31,6804.93) ; L1.2@5915,3841.89 5885.63,3841.89 C4.2@5885.63,3750 5885.63,3746.62 5964.37,3667.88 6137.88,3667.88 U3.1@6153.1,3683.1 ; v2(6110,3600) v2(6153.1,3600) ; v2(6197.69,3600) v2(6153.1,3600) ; v2(6347.3,3832.3) v2(6315.52,3800.52) v2(6282.5,3767.5) 6216.5,3767.5 U3.1@6157.59,3708.59 ; CN2.8@6388.09,6381.52 v1(6490.31,6381.52) v1(6525.31,6381.52) ; CN5.8@6621.38,4252.8 6621.38,4299.35 v2(6651.45,4329.42) ; 7011.1,3395.18 SW2.2@7011.1,3470 ; 7048.25,3868.17 7051.78,3864.63 7094.16,3822.25 7094.16,3821.33 7123.13,3792.37 7193.06,3792.37 H1.3@7243.61,3741.82 7193.06,3691.27 7193.06,3443.06 7145,3395 7011.28,3395 6727.84,3395 6537.84,3585 6432.99,3585 6375,3585 v2(6273.35,3483.35) v2(6241.57,3451.57) v2(6208.54,3418.54) 6170,3380 5250,3380 4905.41,3380 4757.01,3528.41 4757.01,3594.39 ; v2(6153.1,3600) U3.1@6153.1,3683.1 ; U3.1@6153.1,3683.1 6157.59,3687.59 U3.1@6157.59,3708.59 ; U3.1@6153.1,3683.1 6153.1,3704.1 U3.1@6157.59,3708.59
  Bottom Layer w6: v1(4825.31,6734.93) v1(5385.89,6734.93) ; v1(5064.49,5075.31) v1(5625.07,5075.31)
  Bottom Layer w10: v1@4695.07,5086.9 4788.48,5180.31 4830.07,5180.31 4850.07,5160.31 4850.07,5095.31 4870.07,5075.31 v1(5064.49,5075.31) ; v1(5385.89,6734.93) 5580.31,6734.93 5600.31,6714.93 5600.31,6649.93 5620.31,6629.93 5661.9,6629.93 v1@5755.31,6723.34
  Bottom Layer w20: v2(3740.12,4334.34) 3769.46,4305 4712.03,4305 ; 3.3V.1@3876.06,5432.64 3879.98,5428.71 v1(3925.07,5428.71) v1(3960.07,5428.71) 3960.07,5280.31 4265.07,4975.31 v1(4290.2,4975.31) 4675.07,4975.31 4695.07,4995.31 v1(4695.07,5005.31) v1(4695.07,5044.53) v1(4695.07,5085.31) ; v2(4711.57,4336.02) 4712.03,4335.55 4712.03,4305 ; v2(5685,4340) 5685,4307.33 5682.67,4305 ; v1(5755.31,6724.93) v1(5755.31,6765.7) v1(5755.31,6804.93) 5755.31,6814.93 5775.31,6834.93 v1(6160.19,6834.93) 6185.31,6834.93 6490.31,6529.93 v1(6490.31,6381.52) v1(6525.31,6381.52) 6570.4,6381.52 3.3V.1@6574.32,6377.59 ; v2(6110,3600) v2(6153.1,3600) v2(6197.69,3600) 6273.35,3524.35 v2(6273.35,3483.35) v2(6241.57,3451.57) v2(6208.54,3418.54) ; v2(6282.5,3767.5) v2(6315.52,3800.52) v2(6347.3,3832.3) 6420,3905 6421.77,3905 6454.8,3938.02 6483.77,3938.02 6530.75,3985 6530.75,4040.75 6651.45,4161.45 6651.45,4305 ; v2(6651.45,4329.42) 6651.45,4305 ; 4712.03,4305 5682.67,4305 ; 5682.67,4305 6651.45,4305
24V: C2.2 C13.2 C14.2 C15.2 C16.2 D4.2 U1.3@5644.76,3842.6 U4.1@5488.3,3708.59 U8.5 U9.5 U10.5@4824.08,3925.81 U11.5 | length 2534.4
  Top Layer w20: U8.5@4179.08,3925.85 4179.08,3913.48 v2(4222.06,3870.5) C13.2@4255,3837.56 ; U9.5@4504.08,3925.77 4504.08,3913.56 v2(4547.36,3870.29) C15.2@4580,3837.64 ; U10.5@4824.08,3925.81 4824.08,3913.52 C14.2@4900,3837.6 ; U11.5@5144.08,3925.73 5144.08,3913.6 v2(5185.04,3872.64) C16.2@5220,3837.69 ; v2(5313.98,3870.95) v2@5330,3870.95 ; C2.2@5330,3812.3 v2@5330,3870.95 ; 5470,3835.63 5470,3840.82 5435.12,3840.82 v2(5405,3870.95) v2(5364.93,3870.95) v2@5330,3870.95
  Top Layer w40: v5(3960,3775) v5(3960,3716.2) v5(3960,3656.92) 4009.49,3607.43 D4.2@4019.49,3607.43
  Bottom Layer w20: v2(5313.98,3870.95) v2(5364.93,3870.95) v2(5405,3870.95)
  Bottom Layer w40: v5(3960,3656.92) v5(3960,3716.2) v5(3960,3775) 3960,3813.78 4017.16,3870.95 v2(4867.28,3870.95) v2(5313.98,3870.95)
$1N1340: C17.1 D3.2 U7.5 | length 222.2
  Top Layer w6: C17.1@5557.44,3435 5570,3447.56 5570,3462.32 5617.68,3510 D3.2@5626.16,3510 5629.78,3510 5688.58,3568.8 U7.5@5715.62,3568.8
$1N2752: C5.2 L1.1 U1.2@5644.76,3880 | length 448.7
  Top Layer w20: U1.2@5649.76,3880 5678.04,3880 5692.19,3894.14 5692.19,4067.19 5703.11,4078.11 L1.1@5915,4078.11
$1N2756: C5.1 U1.6@5735.24,3917.4 | length 93.6
  Top Layer w10: U1.6@5735.24,3917.4 5735.24,4007.68 C5.1@5737.56,4010
$1N6554: C1.1 R1.1@5795,3718.66 R2.2@5736,3718.66 U1.4@5735.24,3842.6 | length 183.3
  Top Layer w10: U1.4@5735.24,3842.6 5736,3841.84 R2.2@5736,3718.66 R1.1@5795,3718.66
$1N10852: LED1.2@4675.27,6427.42 LED1.2@5775.11,5382.81 LED2.4 | length 1251.9
  Top Layer w6: LED1.2@4675.27,6427.42 4667.81,6427.42 4635.31,6459.93 4635.31,6599.93 4903.38,6868 LED2.4@4903.38,6921.42 ; LED2.4@5547,4888.81 5547,4942.24 5815.07,5210.31 5815.07,5350.31 5782.57,5382.81 LED1.2@5775.11,5382.81
$1N13047: R1.2@5070.99,5191.81 R1.2@5379.39,6618.42 U7.1@4801.8,4730.81 U7.1@5648.58,7079.42 | length 1243.9
  Top Layer w6: U7.1@4801.8,4730.81 4801.8,4765.04 4940.32,4903.56 4940.32,5145.55 4986.58,5191.81 R1.2@5070.99,5191.81 ; R1.2@5379.39,6618.42 5463.8,6618.42 5510.06,6664.68 5510.06,6906.67 5648.58,7045.19 U7.1@5648.58,7079.42
$1N17664: R3.1@4043.26,4050 U8.7 | length 139
  Top Layer w20: R3.1@4043.26,4050 4043.26,3976.74 4079.08,3940.92 U8.7@4079.08,3925.85
$1N17864: R4.1@4368.26,4054.68 U9.7 | length 143.7
  Top Layer w20: R4.1@4368.26,4054.68 4368.26,3981.74 4404.08,3945.92 U9.7@4404.08,3925.77
$1N18070: R5.1@4688.26,4052.34 U10.7@4724.08,3925.81 | length 141.4
  Top Layer w20: R5.1@4688.26,4052.34 4688.26,3971.74 4724.08,3935.92 U10.7@4724.08,3925.81
$1N18276: R6.1@5008.26,4057.02 U11.7 | length 146.1
  Top Layer w20: R6.1@5008.26,4057.02 5008.26,3971.74 5044.08,3935.92 U11.7@5044.08,3925.73
$1N22933: CN1.1 D2.1 R7.2 R9.2 | length 1775.8
  Top Layer w10: v1(4969.51,3459.51) 5001.42,3427.6 D2.1@5008.36,3427.6 5067.26,3427.6 R9.2@5075,3435.34 5080.34,3430 R7.2@5140.34,3430
  Bottom Layer w10: CN1.1@3780.95,3870.95 3785,3866.89 3785,3652.57 3873.56,3564.02 4865,3564.02 4882.36,3546.65 cw(c4873.52,3537.81) 4882.36,3528.98 4874.46,3521.07 ccw(c4883.3,3512.24) 4892.14,3503.4 4900.04,3511.3 cw(c4908.88,3502.46) 4917.72,3493.62 4909.82,3485.72 ccw(c4918.65,3476.88) 4927.49,3468.04 4935.4,3475.94 cw(c4944.23,3467.1) 4953.07,3475.94 v1(4969.51,3459.51)
$1N22936: CN1.3 D2.2 R8.2 R9.1 | length 1775.8
  Top Layer w10: v1(4960,3505) 5005.76,3505 D2.2@5008.36,3502.4 5067.26,3502.4 R9.1@5075,3494.66 5080.34,3500 R8.2@5140.34,3500
  Bottom Layer w10: CN1.3@3780.95,3989.05 3834.68,3935.32 3834.68,3830.41 3800.98,3796.71 3800.98,3659.19 3880.18,3580 4885,3580 v1(4960,3505)
$1N32139: Q1.2 R10.2 R11.2 | length 147
  Top Layer w6: R11.2@5326.86,3429.1 R10.2@5326.86,3500 5339.7,3512.85 Q1.2@5397.6,3512.85
$1N32182: C17.2 Q1.3 U7.8 | length 323.8
  Top Layer w6: Q1.3@5435,3422.29 5452.29,3405 5612.56,3405 5612.56,3405.73 ; C17.2@5612.56,3435 5612.56,3405.73 ; U7.8@5715.62,3418.8 5663.8,3418.8 5650,3405 5613.29,3405 5612.56,3405.73
$1N32717: CN1.4 D1.2 D4.1 | length 834.7
  Top Layer w40: D1.2@3822.98,3460 3822.98,3606.8 D4.1@3822.35,3607.43 3822.35,3651.38 3715,3758.73 3715,4020 3755,4060 3828.11,4060 CN1.4@3899.05,3989.05
BOOT0: RN3.1 SW2.1 U2.44 | length 766.4
  Top Layer w6: v1(6558.74,3991.26) 6559.9,3992.41 RN3.1@6559.9,4055.5 ; v1(6740.56,3775) U2.44@6740.56,3618.64 6740.56,3487.3 6757.86,3470 SW2.1@6830,3470
  Bottom Layer w6: v1(6558.74,3991.26) 6558.74,3946.82 6594.57,3910.99 6638.7,3910.99 6680,3869.69 6680,3835.56 v1(6740.56,3775)
BOOT1: RN3.2 U2.20 | length 177
  Top Layer w6: RN3.2@6591.39,4055.5 6591.39,4018.61 6604.19,4005.81 6668.19,4005.81 6681.5,3992.5 U2.20@6681.5,3953.28
EXIT_RX: H1.2 U2.22 | length 1470.9
  Top Layer w6: v1(6630,3890) 6642.13,3902.13 U2.22@6642.13,3953.28
  Bottom Layer w6: v1(6630,3890) 6519.16,3890 6489.15,3920.02 6488.84,3920.02 6487.84,3921.01 6461.84,3921.01 6380,3839.16 6380,3808.92 6473.51,3715.41 6516.05,3715.41 6592.31,3639.15 6668.81,3639.15 6738.43,3569.53 6878.94,3569.53 7098.76,3789.35 7191.15,3789.35 H1.2@7243.61,3841.82
EXIT_TX: H1.1 U2.21 | length 1563.1
  Top Layer w6: v1(6653.2,3865) 6653.2,3907.29 6661.82,3915.9 U2.21@6661.82,3953.28
  Bottom Layer w6: v1(6653.2,3865) 6530,3865 6485,3910 6484.69,3910 6483.7,3910.99 6466.3,3910.99 6465.31,3910 6465,3910 6390.02,3835.02 6390.02,3813.07 6477.66,3725.42 6520.2,3725.42 6596.46,3649.16 6672.96,3649.16 6742.58,3579.54 6874.79,3579.54 7094.61,3799.37 7161.2,3799.37 7195,3833.17 7195,3893.2 H1.1@7243.61,3941.82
